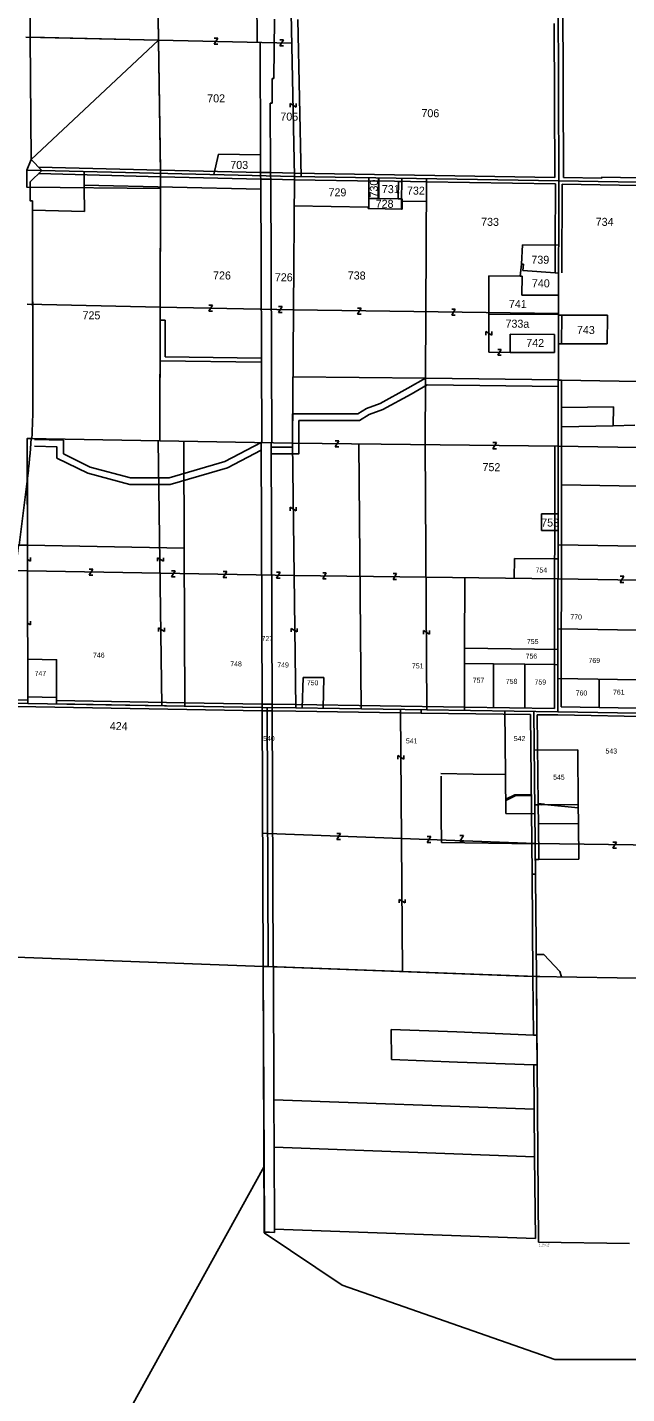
# Model space of a CAD drawing. Extents: x 582596 to 627039, y 145946 to 197316.
# Drawn here: x 604634 to 610608, y 158044 to 171651 of the extents above; entities that cross this region are included whole.
import ezdxf

# ---------------------------------------------------------------- set-up
doc = ezdxf.new("R2010")
doc.units = 0
for name, color, linetype in [('Defpoints 2', 7, 'Continuous'), ('E_RW_CorporateLimits', 7, 'Continuous'), ('E_RW_EasementUtility', 7, 'Continuous'), ('E_RW_Existing', 7, 'Continuous'), ('E_RW_SixteenthLine', 7, 'Continuous'), ('Kenosha_County_Parcels_KCCS_05232018', 7, 'Continuous'), ('P_MISC_NoPlot', 7, 'Continuous'), ('P_RW_MinorLotLine', 7, 'Continuous'), ('P_RW_PropertyConnector', 7, 'Continuous'), ('P_RW_PropertyLine', 7, 'Continuous'), ('P_RW_QuarterLine', 7, 'Continuous'), ('P_RW_SectionLine', 7, 'Continuous'), ('P_RW_Text', 7, 'Continuous')]:
    doc.layers.add(name, color=color, linetype=linetype)

msp = doc.modelspace()

# ---------------------------------------------------------------- linework, layer by layer
at = {"layer": 'Defpoints'}
msp.add_lwpolyline([(604688, 168216), (604688, 168216)], dxfattribs=at)
msp.add_lwpolyline([(604688, 168216), (604688, 168216)], dxfattribs=at)
at = {"layer": 'E_RW_CorporateLimits'}
msp.add_lwpolyline([(607310, 164873), (606975, 164878)], dxfattribs=at)
at = {"layer": 'E_RW_EasementUtility'}
for p, q in [((606008, 168734), (606007, 168369)), ((605957, 168330), (606965, 168316)), ((606007, 168369), (606966, 168356)), ((609726, 163922), (609789, 163916)), ((609726, 163912), (609759, 163909)), ((609789, 163909), (609789, 163916)), ((609789, 163911), (610126, 163877))]:
    msp.add_line(p, q, dxfattribs=at)
for points in [[(605958, 168735), (606008, 168734)], [(607064, 167471), (607276, 167471), (607276, 167801), (607927, 167801), (608014, 167855), (608151, 167904), (608427, 168057), (608604, 168157), (609927, 168141)], [(607064, 167405), (607342, 167404), (607342, 167735), (607946, 167735), (608043, 167795), (608178, 167844), (608459, 167999), (608621, 168091), (609927, 168075)], [(604707, 167547), (604993, 167539), (604995, 167404), (605259, 167272), (605663, 167164), (606048, 167164), (606604, 167327), (606964, 167515)], [(604706, 167481), (604928, 167475), (604929, 167362), (605236, 167210), (605655, 167098), (606057, 167098), (606629, 167265), (606965, 167441)], [(609659, 164010), (609495, 164008), (609402, 163963)], [(609659, 164000), (609498, 163998), (609403, 163952)]]:
    msp.add_lwpolyline(points, dxfattribs=at)
at = {"layer": 'E_RW_Existing'}
for p, q in [((609977, 170155), (609969, 172767)), ((609892, 170157), (609887, 171690)), ((604746, 170260), (605962, 170230)), ((605962, 170230), (606959, 170206)), ((604746, 170194), (605963, 170164)), ((605963, 170164), (606960, 170140)), ((607059, 170204), (607297, 170198)), ((607060, 170138), (607295, 170132)), ((607295, 170132), (608133, 170119)), ((607297, 170198), (609892, 170157)), ((608133, 170122), (608614, 170114)), ((608614, 170111), (609899, 170091)), ((609899, 170091), (609897, 169483)), ((609977, 170155), (610361, 170148)), ((609965, 170090), (609963, 169205)), ((609965, 170090), (612570, 170042)), ((604634, 167558), (604674, 167555)), ((604674, 167555), (604679, 167555)), ((609893, 167480), (609889, 165305)), ((609958, 166496), (609955, 165166)), ((604926, 164946), (606205, 164924)), ((606205, 164924), (606975, 164911)), ((606975, 164845), (607075, 164844)), ((607075, 164910), (607310, 164906)), ((607075, 164844), (607310, 164840)), ((607310, 164906), (608992, 164882)), ((607310, 164840), (608560, 164822)), ((608560, 164822), (609651, 164807)), ((609666, 163217), (609651, 164807)), ((609717, 164806), (609921, 164803)), ((609726, 163908), (609717, 164806)), ((609921, 164803), (612544, 164757))]:
    msp.add_line(p, q, dxfattribs=at)
for points in [[(610361, 170148), (610361, 170160), (610921, 170150)], [(604662, 170060), (604663, 169922), (604685, 169922)], [(604685, 169922), (604688, 167918)], [(604635, 167158), (604552, 166495), (604502, 166495)], [(604638, 164918), (604307, 164924), (604502, 166495), (604547, 166495), (604371, 165076), (604477, 164954), (604638, 164951), (604638, 164918)], [(606975, 164845), (604340, 164890), (604377, 162397), (604344, 162398), (604307, 164924), (604638, 164918)], [(604638, 164918), (606975, 164878)]]:
    msp.add_lwpolyline(points, dxfattribs=at)
msp.add_arc((598904, 167907), 5785, 356.5279, 0.1015, dxfattribs=at)
at = {"layer": 'E_RW_SixteenthLine'}
for p, q in [((605923, 172850), (605943, 171524)), ((605943, 171524), (604618, 171553)), ((605943, 171524), (605962, 170197)), ((605943, 171524), (607268, 171495)), ((605962, 170197), (605962, 170045)), ((608614, 170144), (608601, 167494)), ((605962, 170045), (605955, 167534)), ((605962, 170044), (605955, 167534)), ((605959, 168865), (604631, 168894)), ((605959, 168865), (607286, 168837)), ((607286, 168837), (609929, 168801)), ((605974, 164895), (605939, 167534)), ((608601, 167494), (608616, 164854)), ((604636, 166238), (601992, 166283)), ((607293, 166191), (604636, 166238)), ((607293, 166191), (609924, 166158)), ((609924, 166158), (612565, 166112)), ((608373, 162248), (608355, 164858)), ((606981, 163626), (607031, 163624)), ((607031, 163624), (609697, 163524)), ((609697, 163524), (612357, 163488))]:
    msp.add_line(p, q, dxfattribs=at)
at = {"layer": 'Kenosha_County_Parcels_KCCS_05232018'}
for points in [[(606991, 160871), (606997, 159690), (606997, 159690), (606997, 159687), (606997, 159687), (606997, 159687), (606996, 159688)], [(606996, 159654), (606996, 159654), (606996, 159645)]]:
    msp.add_lwpolyline(points, dxfattribs=at)
at = {"layer": 'P_MISC_NoPlot'}
for points in [[(606994, 160308), (600102, 147850), (582596, 147850), (584141, 197316), (605972, 196079), (609782, 181858), (607213, 178117), (605888, 178149), (605896, 176823), (605905, 175497), (605914, 174174), (605923, 172850), (605943, 171524), (604673, 170334), (604629, 170230), (604629, 170060), (605962, 170045), (605959, 168865), (605955, 167534), (604634, 167558), (604638, 164918), (606975, 164878), (606986, 162297)], [(606994, 160308), (600102, 147850), (582596, 147850), (584141, 197316), (605972, 196079), (609782, 181858), (607213, 178117), (605888, 178149), (605896, 176823), (605905, 175497), (605914, 174174), (605923, 172850), (605943, 171524), (604673, 170334), (604629, 170230), (604629, 170060), (605962, 170045), (605959, 168865), (605955, 167534), (604634, 167558), (604638, 164918), (606975, 164878), (606986, 162297)], [(606994, 160308), (600102, 147850), (582596, 147850), (584141, 197316), (605972, 196079), (609782, 181858), (607213, 178117), (605888, 178149), (605896, 176823), (605905, 175497), (605914, 174174), (605923, 172850), (605943, 171524), (604673, 170334), (604629, 170230), (604629, 170060), (605962, 170045), (605959, 168865), (605955, 167534), (604634, 167558), (604638, 164918), (606975, 164878), (606986, 162297)], [(606996, 159645), (606986, 162297), (606975, 164878), (604638, 164918), (604634, 167558), (605955, 167534), (605962, 170045), (604629, 170060), (604629, 170230), (604673, 170334), (605943, 171524), (605923, 172850), (605914, 174174), (605905, 175497), (605896, 176823), (605888, 178149), (607213, 178117), (607213, 178117), (627039, 170601), (626501, 158386), (609891, 158386), (607773, 159126)]]:
    msp.add_lwpolyline(points, close=True, dxfattribs=at)
at = {"layer": 'P_RW_MinorLotLine'}
for p, q in [((607375, 164872), (607383, 165176)), ((607383, 165176), (607588, 165175)), ((607588, 165175), (607584, 164869))]:
    msp.add_line(p, q, dxfattribs=at)
at = {"layer": 'P_RW_PropertyConnector'}
for p, q in [((606498, 171542), (606534, 171542)), ((606534, 171542), (606498, 171482)), ((606498, 171482), (606534, 171482)), ((606516, 171512), (606516, 171512)), ((607150, 171528), (607186, 171528)), ((607186, 171528), (607150, 171468)), ((607150, 171468), (607186, 171468)), ((607168, 171498), (607168, 171498)), ((607253, 170856), (607253, 170892)), ((607253, 170892), (607313, 170856)), ((607283, 170874), (607283, 170874)), ((607313, 170856), (607313, 170892)), ((606443, 168884), (606479, 168884)), ((606479, 168884), (606443, 168824)), ((607138, 168872), (607174, 168872)), ((607174, 168872), (607138, 168812)), ((606443, 168824), (606479, 168824)), ((606461, 168854), (606461, 168854)), ((607138, 168812), (607174, 168812)), ((607156, 168842), (607156, 168842)), ((607925, 168854), (607961, 168854)), ((607961, 168854), (607925, 168794)), ((607925, 168794), (607961, 168794)), ((607943, 168824), (607943, 168824)), ((608864, 168846), (608899, 168846)), ((608899, 168846), (608864, 168786)), ((608864, 168786), (608899, 168786)), ((608881, 168816), (608881, 168816)), ((609203, 168587), (609203, 168623)), ((609203, 168623), (609263, 168587)), ((609233, 168605), (609233, 168605)), ((609263, 168587), (609263, 168623)), ((609323, 168444), (609358, 168444)), ((609358, 168444), (609323, 168385)), ((609323, 168385), (609358, 168385)), ((609341, 168415), (609341, 168415)), ((607704, 167534), (607739, 167534)), ((607739, 167534), (607704, 167474)), ((609273, 167515), (609309, 167515)), ((609309, 167515), (609273, 167455)), ((607704, 167474), (607739, 167474)), ((607721, 167504), (607721, 167504)), ((609273, 167455), (609309, 167455)), ((609291, 167485), (609291, 167485)), ((607253, 166837), (607253, 166873)), ((607253, 166873), (607313, 166837)), ((607283, 166855), (607283, 166855)), ((607313, 166837), (607313, 166873)), ((604636, 166352), (604666, 166334)), ((604636, 166352), (604636, 166352)), ((604666, 166334), (604666, 166370)), ((605931, 166334), (605931, 166369)), ((605931, 166369), (605991, 166334)), ((605961, 166352), (605961, 166352)), ((605991, 166334), (605991, 166369)), ((605252, 166256), (605287, 166256)), ((605287, 166256), (605252, 166196)), ((605252, 166196), (605287, 166196)), ((605269, 166226), (605269, 166226)), ((606071, 166240), (606107, 166240)), ((606107, 166240), (606071, 166180)), ((606071, 166180), (606107, 166180)), ((606089, 166210), (606089, 166210)), ((606587, 166232), (606623, 166232)), ((606623, 166232), (606587, 166172)), ((606587, 166172), (606623, 166172)), ((606605, 166202), (606605, 166202)), ((607119, 166225), (607154, 166225)), ((607154, 166225), (607119, 166165)), ((607119, 166165), (607154, 166165)), ((607136, 166195), (607136, 166195)), ((607578, 166218), (607614, 166218)), ((607614, 166218), (607578, 166158)), ((607578, 166158), (607614, 166158)), ((607596, 166188), (607596, 166188)), ((608279, 166211), (608315, 166211)), ((608315, 166211), (608279, 166151)), ((608279, 166151), (608315, 166151)), ((608297, 166181), (608297, 166181)), ((610543, 166184), (610579, 166184)), ((610579, 166184), (610543, 166124)), ((610561, 166154), (610561, 166154)), ((610543, 166124), (610579, 166124)), ((604667, 165701), (604667, 165736)), ((604637, 165718), (604667, 165701)), ((605943, 165636), (605943, 165672)), ((605943, 165672), (606003, 165636)), ((605973, 165654), (605973, 165654)), ((606003, 165636), (606003, 165672)), ((607265, 165630), (607265, 165665)), ((607265, 165665), (607325, 165630)), ((607295, 165648), (607295, 165648)), ((607325, 165630), (607325, 165665)), ((608584, 165645), (608584, 165609)), ((608644, 165609), (608584, 165645)), ((608614, 165627), (608614, 165627)), ((608644, 165645), (608644, 165609)), ((608328, 164362), (608328, 164398)), ((608328, 164398), (608388, 164362)), ((608358, 164380), (608358, 164380)), ((608388, 164362), (608388, 164398)), ((607720, 163622), (607755, 163622)), ((607755, 163622), (607720, 163562)), ((607720, 163562), (607755, 163562)), ((607737, 163592), (607737, 163592)), ((608621, 163592), (608657, 163592)), ((608657, 163592), (608621, 163532)), ((608639, 163562), (608639, 163562)), ((608945, 163602), (608981, 163602)), ((608981, 163602), (608945, 163542)), ((608963, 163572), (608963, 163572)), ((608621, 163532), (608657, 163532)), ((608945, 163542), (608981, 163542)), ((610471, 163538), (610507, 163538)), ((610507, 163538), (610471, 163478)), ((610471, 163478), (610507, 163478)), ((610489, 163508), (610489, 163508)), ((608339, 162931), (608339, 162967)), ((608339, 162967), (608399, 162931)), ((608369, 162949), (608369, 162949)), ((608399, 162931), (608399, 162967))]:
    msp.add_line(p, q, dxfattribs=at)
at = {"layer": 'P_RW_PropertyLine'}
for p, q in [((606924, 171503), (606918, 172831)), ((607097, 171734), (607090, 171142)), ((607329, 171730), (607363, 170164)), ((605961, 170229), (605942, 171523)), ((605942, 171523), (605961, 170229)), ((606959, 170382), (606954, 171502)), ((607090, 171142), (607075, 171142)), ((607075, 171142), (607076, 170897)), ((607076, 170897), (607056, 170897)), ((607056, 170897), (607059, 170204)), ((606493, 170184), (606541, 170387)), ((606541, 170387), (606959, 170382)), ((606959, 170382), (606959, 170206)), ((604662, 170112), (604779, 170226)), ((604779, 170226), (604673, 170334)), ((605961, 170196), (605961, 170229)), ((605961, 170229), (605961, 170196)), ((604662, 170060), (604662, 170112)), ((604777, 170225), (604778, 170225)), ((605200, 170215), (605199, 170215)), ((605199, 170215), (605200, 170215)), ((605202, 170054), (605201, 170216)), ((606959, 170206), (606959, 170173)), ((607059, 170204), (606959, 170206)), ((606959, 170173), (606960, 170140)), ((606959, 170140), (607060, 170138)), ((606960, 170140), (606971, 167515)), ((607059, 170171), (607059, 170204)), ((607060, 170138), (607059, 170171)), ((607060, 170138), (607071, 167513)), ((608039, 170152), (608037, 169947)), ((608037, 169947), (608039, 170152)), ((608133, 170150), (608132, 169945)), ((608132, 169945), (608133, 170150)), ((608137, 169945), (608139, 170150)), ((608139, 170150), (608137, 169945)), ((608333, 170117), (608332, 169942)), ((608332, 169942), (608333, 170117)), ((608366, 170117), (608333, 170117)), ((608333, 170117), (608366, 170117)), ((608365, 169942), (608366, 170117)), ((608366, 170117), (608365, 169942)), ((608366, 170147), (608366, 170117)), ((608366, 170117), (608366, 170147)), ((608612, 170110), (608614, 170114)), ((608614, 170114), (608612, 170110)), ((608614, 170114), (608613, 169918)), ((608614, 170114), (608614, 170144)), ((608614, 170144), (608614, 170114)), ((605202, 170081), (606960, 170038)), ((607294, 169872), (608032, 169860)), ((608032, 169860), (607294, 169872)), ((608032, 169860), (608032, 169847)), ((608037, 169860), (608032, 169860)), ((608032, 169847), (608032, 169860)), ((608032, 169860), (608037, 169860)), ((608032, 169847), (608037, 169847)), ((608037, 169847), (608032, 169847)), ((608037, 169947), (608037, 169860)), ((608132, 169945), (608037, 169947)), ((608037, 169860), (608037, 169947)), ((608037, 169947), (608132, 169945)), ((608037, 169847), (608037, 169860)), ((608037, 169860), (608037, 169847)), ((608037, 169847), (608365, 169842)), ((608365, 169842), (608037, 169847)), ((608132, 169945), (608137, 169945)), ((608137, 169945), (608132, 169945)), ((608332, 169942), (608137, 169945)), ((608137, 169945), (608332, 169942)), ((608332, 169942), (608365, 169942)), ((608365, 169942), (608332, 169942)), ((608365, 169942), (608365, 169921)), ((608370, 169942), (608365, 169942)), ((608365, 169921), (608365, 169942)), ((608365, 169942), (608370, 169942)), ((608365, 169921), (608365, 169842)), ((608365, 169842), (608365, 169921)), ((608365, 169921), (608370, 169921)), ((608370, 169921), (608365, 169921)), ((608365, 169842), (608370, 169842)), ((608370, 169842), (608365, 169842)), ((608370, 169921), (608370, 169942)), ((608370, 169942), (608370, 169921)), ((608370, 169842), (608370, 169921)), ((608370, 169921), (608611, 169917)), ((608613, 169918), (608370, 169921)), ((608370, 169921), (608370, 169842)), ((609570, 169484), (609560, 169294)), ((609930, 169483), (609570, 169484)), ((609897, 169483), (609897, 169206)), ((609560, 169294), (609545, 169174)), ((609580, 169294), (609560, 169294)), ((609572, 169229), (609580, 169294)), ((609235, 169175), (609234, 168795)), ((609545, 169174), (609235, 169175)), ((609235, 169175), (609545, 169174)), ((609545, 169174), (609565, 169174)), ((609565, 169174), (609545, 169174)), ((609565, 169174), (609564, 168984)), ((609897, 169206), (609572, 169229)), ((609897, 169206), (609930, 169203)), ((609564, 168984), (609896, 168983)), ((609896, 168983), (609929, 168983)), ((609929, 168983), (609896, 168983)), ((609234, 168795), (609233, 168415)), ((609929, 168793), (609234, 168795)), ((609929, 168785), (609929, 168793)), ((609961, 168785), (609929, 168785)), ((609960, 168500), (609961, 168785)), ((610416, 168784), (609961, 168785)), ((610415, 168499), (610416, 168784)), ((609448, 168414), (609448, 168594)), ((609448, 168594), (609888, 168593)), ((609888, 168593), (609888, 168413)), ((609928, 168500), (609960, 168500)), ((609960, 168500), (610262, 168500)), ((610262, 168500), (609960, 168500)), ((610262, 168500), (610415, 168499)), ((609233, 168415), (609448, 168414)), ((609888, 168413), (609448, 168414)), ((608604, 168157), (607280, 168171)), ((608604, 168157), (609927, 168141)), ((609960, 168139), (609927, 168139)), ((609959, 167865), (609960, 168139)), ((611247, 168116), (609960, 168139)), ((609960, 168139), (611247, 168116)), ((610477, 167872), (609959, 167865)), ((609959, 167865), (610477, 167872)), ((609959, 167672), (609959, 167865)), ((610474, 167683), (610477, 167872)), ((610477, 167872), (610474, 167683)), ((609958, 167096), (609959, 167672)), ((609959, 167672), (610474, 167683)), ((610474, 167683), (609959, 167672)), ((610474, 167683), (610691, 167688)), ((610691, 167688), (610474, 167683)), ((604673, 167557), (604678, 167557)), ((606194, 167529), (606198, 166464)), ((606964, 167515), (606975, 164877)), ((607064, 167513), (607075, 164878)), ((607938, 167502), (607963, 164863)), ((604635, 167158), (604645, 167240)), ((609957, 166498), (609958, 167096)), ((609958, 167096), (611246, 167074)), ((609760, 166641), (609760, 166806)), ((609760, 166806), (609925, 166805)), ((609925, 166640), (609760, 166641)), ((604636, 166493), (606198, 166464)), ((606198, 166464), (606204, 164891)), ((609924, 166498), (611245, 166476)), ((609489, 166363), (609488, 166163)), ((609891, 166358), (609489, 166363)), ((609924, 166358), (609891, 166358)), ((608994, 166169), (608993, 165467)), ((611243, 165639), (609923, 165662)), ((609923, 165454), (608993, 165467)), ((608993, 165317), (608993, 165467)), ((604638, 165358), (604925, 165353)), ((604925, 165353), (604926, 164913)), ((608993, 165317), (608992, 164882)), ((608993, 165317), (609282, 165313)), ((609282, 164878), (609282, 165313)), ((609282, 165313), (609592, 165309)), ((609592, 165309), (609592, 164874)), ((609592, 165309), (609889, 165305)), ((609922, 165304), (609889, 165305)), ((609889, 165305), (609889, 164869)), ((611242, 165143), (609922, 165166)), ((609955, 165166), (609955, 164885)), ((610335, 165159), (610334, 164879)), ((604638, 164983), (604926, 164978)), ((606975, 164911), (607075, 164910)), ((606975, 164878), (606986, 162297)), ((607075, 164877), (607086, 162297)), ((608560, 164825), (608560, 164855)), ((608992, 164882), (608992, 164849)), ((608992, 164882), (609889, 164869)), ((609394, 164843), (609400, 164211)), ((609955, 164885), (610714, 164872)), ((610121, 164457), (609688, 164453)), ((610126, 163912), (610121, 164457)), ((608757, 164220), (609078, 164215)), ((608758, 164007), (608758, 164193)), ((609078, 164215), (609400, 164211)), ((609400, 164211), (609404, 163823)), ((608760, 163790), (608758, 164007)), ((609726, 163908), (609693, 163908)), ((610126, 163912), (609726, 163908)), ((609726, 163908), (609728, 163718)), ((610126, 163912), (610128, 163722)), ((608763, 163532), (608760, 163790)), ((609404, 163823), (609694, 163819)), ((610128, 163722), (609728, 163718)), ((609728, 163718), (609731, 163364)), ((610131, 163367), (610128, 163722)), ((609697, 163519), (608763, 163532)), ((609698, 163363), (609731, 163364)), ((609698, 163363), (609699, 163217)), ((609699, 163217), (609698, 163363)), ((609731, 163364), (610131, 163367)), ((609699, 163217), (609665, 163217)), ((609665, 163217), (609674, 162199)), ((609781, 162417), (609707, 162418)), ((609941, 162248), (609781, 162417)), ((607087, 162305), (607087, 162295)), ((607087, 162295), (607087, 162305)), ((607087, 162295), (607092, 160972)), ((607092, 160972), (607087, 162295)), ((607087, 162295), (607087, 162295)), ((607087, 162295), (607105, 162294)), ((607089, 162295), (607087, 162295)), ((607087, 162295), (607087, 162295)), ((607105, 162294), (607089, 162295)), ((607105, 162294), (609674, 162199)), ((609674, 162199), (607105, 162294)), ((609674, 162199), (609681, 161616)), ((609957, 162194), (609941, 162248)), ((609714, 161615), (609709, 162198)), ((609709, 162198), (609742, 162197)), ((608264, 161371), (608261, 161671)), ((608261, 161671), (608914, 161647)), ((608914, 161647), (608261, 161671)), ((608261, 161671), (608264, 161371)), ((608914, 161647), (609681, 161616)), ((609681, 161616), (608914, 161647)), ((609681, 161616), (609714, 161615)), ((609714, 161615), (609716, 161318)), ((609716, 161318), (609714, 161615)), ((608923, 161347), (608264, 161371)), ((608264, 161371), (608923, 161347)), ((609683, 161319), (608923, 161347)), ((608923, 161347), (609683, 161319)), ((609716, 161318), (609683, 161319)), ((609683, 161319), (609686, 160876)), ((606998, 159689), (606991, 161001)), ((606991, 161001), (606998, 159689)), ((607092, 160972), (607095, 160500)), ((609686, 160876), (607092, 160972)), ((607095, 160500), (607092, 160972)), ((607092, 160972), (609686, 160876)), ((609686, 160876), (609690, 160403)), ((607099, 159682), (607095, 160500)), ((607095, 160500), (609690, 160403)), ((607095, 160500), (607099, 159682)), ((609690, 160403), (607095, 160500)), ((609690, 160403), (609698, 159591)), ((606998, 159687), (606996, 159687)), ((606996, 159653), (606997, 159658)), ((607002, 159653), (606996, 159653)), ((606997, 159673), (606998, 159687)), ((606997, 159658), (606997, 159673)), ((606998, 159687), (606998, 159689)), ((606998, 159689), (606998, 159689)), ((606998, 159689), (606998, 159689)), ((606998, 159689), (606998, 159687)), ((606998, 159687), (606998, 159687)), ((606998, 159687), (606998, 159687)), ((606998, 159687), (606998, 159687)), ((607037, 159652), (607002, 159653)), ((607047, 159651), (607037, 159652)), ((607099, 159650), (607047, 159651)), ((609698, 159591), (607099, 159682)), ((607099, 159682), (607099, 159677)), ((607099, 159677), (607099, 159663)), ((607099, 159663), (607099, 159655)), ((607099, 159655), (607099, 159650)), ((610636, 159538), (609729, 159552))]:
    msp.add_line(p, q, dxfattribs=at)
for points in [[(605943, 171524), (604663, 171552), (604659, 172015), (605936, 171990), (605943, 171524)], [(605943, 171524), (604663, 171552), (604673, 170334)], [(604688, 167918), (604685, 169830), (605203, 169818), (605202, 170054)], [(605962, 170044), (605955, 167534)], [(605959, 168865), (605955, 167534)], [(604636, 166493), (604552, 166495), (604635, 167158), (604636, 166493)], [(604635, 167158), (604636, 166493)], [(604638, 164951), (604477, 164954), (604371, 165076), (604547, 166495), (604636, 166493)], [(604638, 165358), (604638, 164951)], [(604638, 164918), (604307, 164924), (604344, 162398), (606986, 162299)], [(606205, 164891), (604926, 164913)], [(606975, 164878), (606205, 164891)]]:
    msp.add_lwpolyline(points, dxfattribs=at)
msp.add_lwpolyline([(604638, 164983), (604638, 165358), (604925, 165353), (604926, 164978)], close=True, dxfattribs=at)
for centre, radius, start, end in [((598904, 167907), 5785, 356.5279, 0.1015), ((598812, 167914), 5871, 352.5981, 356.5103), ((598812, 167914), 5871, 352.5981, 356.5103)]:
    msp.add_arc(centre, radius, start, end, dxfattribs=at)
at = {"layer": 'P_RW_QuarterLine'}
for p, q in [((607241, 172825), (607296, 170165)), ((607296, 170165), (607276, 167509)), ((604634, 167558), (605955, 167534)), ((605955, 167534), (607276, 167509)), ((607276, 167509), (607310, 164873)), ((607276, 167509), (609926, 167480)), ((609926, 167480), (612568, 167435)), ((607025, 164877), (607036, 162297)), ((606986, 162299), (607036, 162297)), ((607036, 162297), (609709, 162198)), ((609709, 162198), (612370, 162157))]:
    msp.add_line(p, q, dxfattribs=at)
at = {"layer": 'P_RW_SectionLine'}
for p, q in [((609932, 170123), (609924, 172767)), ((604629, 170230), (607296, 170165)), ((607296, 170165), (609932, 170123)), ((609932, 170123), (609926, 167480)), ((609932, 170123), (612570, 170075)), ((604634, 167558), (604638, 164918)), ((604634, 167558), (605955, 167534)), ((609926, 167480), (609922, 164836)), ((601999, 164961), (604638, 164918)), ((604638, 164918), (606975, 164878)), ((606975, 164878), (604638, 164918)), ((606975, 164878), (607310, 164873)), ((607310, 164873), (609922, 164836)), ((609709, 162198), (609684, 164839)), ((609922, 164836), (612561, 164789)), ((606986, 162299), (604344, 162398)), ((609729, 159552), (609709, 162198))]:
    msp.add_line(p, q, dxfattribs=at)
at = {"layer": 'P_RW_Text'}
msp.add_lwpolyline([(604662, 170060), (604663, 169922), (604685, 169922), (604685, 169830), (605203, 169818), (605202, 170054)], dxfattribs=at)

# ---------------------------------------------------------------- texts
at = {"layer": 'Defpoints 2'}
for s, height, p in [('702', 79.7, (606427, 170904)), ('754', 50, (609700, 166221)), ('770', 50, (610047, 165754)), ('727', 50, (606969, 165539)), ('755', 50, (609614, 165510)), ('746', 50, (605289, 165374)), ('748', 50, (606657, 165287)), ('756', 50, (609601, 165364)), ('769', 50, (610228, 165321)), ('747', 50, (604707, 165192)), ('749', 50, (607126, 165276)), ('751', 50, (608468, 165267)), ('750', 50, (607420, 165099)), ('757', 50, (609074, 165124)), ('758', 50, (609403, 165113)), ('759', 50, (609690, 165106)), ('761', 50, (610472, 165005)), ('760', 50, (610100, 164997)), ('541', 50, (608408, 164520)), ('542', 50, (609483, 164543)), ('543', 50, (610397, 164419)), ('545', 50, (609875, 164159))]:
    msp.add_text(s, height=height, dxfattribs=at).set_placement(p)
for s, height, rotation, p in [('705', 79.7, 359.5042, (607156, 170723)), ('706', 79.7, 359.5042, (608562, 170757)), ('703', 79.7, 359.5042, (606657, 170242)), ('730', 79.7, 89.5042, (608127, 169956)), ('729', 79.7, 359.5042, (607636, 169969)), ('731', 79.7, 359.5042, (608168, 170001)), ('732', 79.7, 359.5042, (608418, 169986)), ('728', 79.7, 359.5042, (608106, 169855)), ('733', 79.7, 359.5042, (609157, 169675)), ('734', 79.7, 359.5042, (610299, 169675)), ('739', 79.7, 359.5042, (609658, 169298)), ('726', 79.7, 359.5042, (606485, 169141)), ('726', 79.7, 359.5042, (607101, 169123)), ('738', 79.7, 359.5042, (607828, 169141)), ('740', 79.7, 359.5042, (609663, 169063)), ('741', 79.7, 359.5042, (609434, 168857)), ('725', 79.7, 359.5042, (605184, 168744)), ('733a', 79.7, 359.5042, (609400, 168661)), ('743', 79.7, 359.5042, (610112, 168598)), ('742', 79.7, 359.5042, (609607, 168469)), ('752', 79.7, 359.5042, (609171, 167232)), ('753', 79.7, 359.5042, (609756, 166680)), ('424', 79.7, 359.5042, (605456, 164653)), ('540', 50, 360, (606984, 164544))]:
    msp.add_text(s, height=height, rotation=rotation, dxfattribs=at).set_placement(p)
at = {"layer": 'P_RW_SectionLine'}
for s, p in [('N=159552.38', (609737, 159527)), ('E=609729.07', (609737, 159507))]:
    msp.add_text(s, height=12, rotation=359.9902, dxfattribs=at).set_placement(p)

doc.saveas('drawing.dxf')
